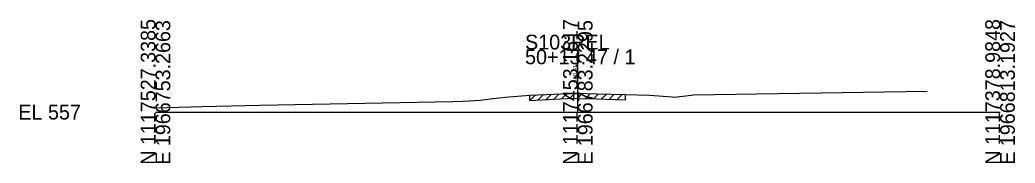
# Model space of a CAD drawing. Extents: x -26 to 163, y -10 to 24518.
# Drawn here: x -25.7 to 162.8, y 490.3 to 517.5 of the extents above; entities that cross this region are included whole.
import ezdxf

# ---------------------------------------------------------------- set-up
doc = ezdxf.new("R2010")
doc.units = 0
for name, color, linetype in [('RD_GPK_XS_Cell', 7, 'Continuous'), ('RD_XS_ExGround', 7, 'Continuous'), ('RD_XS_ExPaveRet', 7, 'Continuous'), ('RD_XS_TX_Elev_EX', 7, 'Continuous')]:
    doc.layers.add(name, color=color, linetype=linetype)

msp = doc.modelspace()

# ---------------------------------------------------------------- linework, layer by layer
at = {"layer": 'RD_GPK_XS_Cell'}
for p, q in [((80, 500), (80, 511.9)), ((0, 500), (80, 500)), ((80, 500), (160, 500))]:
    msp.add_line(p, q, dxfattribs=at)
at = {"layer": 'RD_XS_ExGround'}
msp.add_lwpolyline([(0, 500.8), (8.84, 501.08), (19.79, 501.3), (56.31, 502.02), (58.21, 502.11), (61.59, 502.3), (63.88, 502.58), (66.96, 502.9), (68.59, 503.04), (70.94, 503.22), (75.49, 503.44), (79.16, 503.63), (80, 503.61), (83.59, 503.5), (88.95, 503.33), (93.55, 503.2), (94.47, 503.16), (97.85, 502.9), (98.25, 502.85), (101.55, 503.24), (101.85, 503.3), (146.2, 503.97)], dxfattribs=at)
at = {"layer": 'RD_XS_ExPaveRet'}
for p, q in [((73.94, 502.36), (74.99, 503.42)), ((75.44, 502.44), (76.49, 503.49)), ((76.94, 502.52), (77.99, 503.57)), ((78.44, 502.6), (79.47, 503.62)), ((79.94, 502.61), (80.91, 503.58)), ((81.44, 502.56), (82.41, 503.53)), ((82.94, 502.52), (83.91, 503.49)), ((84.44, 502.47), (85.41, 503.44)), ((85.94, 502.43), (86.91, 503.4)), ((70.94, 502.22), (71.99, 503.27)), ((70.94, 502.22), (70.94, 503.22)), ((70.94, 502.22), (75.49, 502.44)), ((72.44, 502.29), (73.49, 503.34)), ((75.49, 502.44), (79.16, 502.63)), ((79.16, 502.63), (80, 502.61)), ((80, 502.61), (83.59, 502.5)), ((83.59, 502.5), (88.95, 502.33)), ((87.44, 502.38), (88.41, 503.35)), ((88.95, 503.33), (88.95, 502.33))]:
    msp.add_line(p, q, dxfattribs=at)

# ---------------------------------------------------------------- texts
at = {"layer": 'RD_GPK_XS_Cell'}
for s, p in [('N 1117527.3385', (0, 490)), ('E 1966753.2663', (2.8, 490)), ('N 1117453.1617', (80, 490)), ('E 1966783.2295', (82.8, 490)), ('N 1117378.9848', (160, 490)), ('E 1966813.1927', (162.8, 490))]:
    msp.add_text(s, height=2.8, rotation=90, dxfattribs=at).set_placement(p)
for s, p in [('S103REL', (70, 511.9)), ('50+13.47 / 1', (70, 509.1)), ('EL 557', (-26, 498.6))]:
    msp.add_text(s, height=2.8, dxfattribs=at).set_placement(p)
at = {"layer": 'RD_XS_TX_Elev_EX'}
msp.add_text('560.61', height=0.8, rotation=90, dxfattribs=at).set_placement((79.9, 505.61))

doc.saveas('drawing.dxf')
